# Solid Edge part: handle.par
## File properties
Title: Handle
Author: Robert a Rhodes jr
Template: Normal.par
Last saved by: CADCIM
Revision: 5
Application: Solid Edge
Material: aluminum
Accuracy: 0.99
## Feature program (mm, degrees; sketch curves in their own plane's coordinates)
sketch for "unnamed RevolvedProtrusion 1" plane through (0, 0, 0) normal (0, -1, 0) x-axis (1, 0, 0)
  line (-87.868, 0.2971) -> (-87.868, -4)
  line (-87.868, -4) -> (-79.868, -4)
  line (-79.868, -4) -> (-79.868, -5)
  line (-79.868, -5) -> (76.132, -5)
  line (76.132, -5) -> (76.132, -4)
  line (76.132, -4) -> (84.132, -4)
  line (84.132, -4) -> (84.132, 0.2971)
revolve "unnamed RevolvedProtrusion 1" add finite 360 deg about sketch line (-87.868, 0.2971) -> (84.132, 0.2971)
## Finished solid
Body 1: solid body, 7 faces, 6 edges, 0 vertices.
  Faces by surface: plane 4, cylinder 3
  Edges by curve: circle 6
Bounding box of the edges (mm): 172.000 x 10.594 x 10.594, from (-87.868, -5.2971, -5) to (84.132, 5.2971, 5.5941).
Cylindrical faces by radius (mm): R4.2971 x2, R5.2971 x1
Planar faces by outward normal: +x 2, -x 2
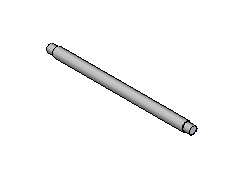
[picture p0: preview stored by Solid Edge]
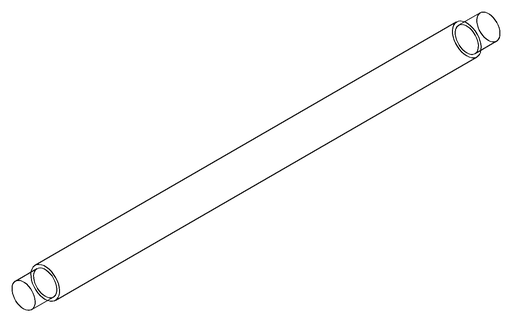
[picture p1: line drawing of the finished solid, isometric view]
